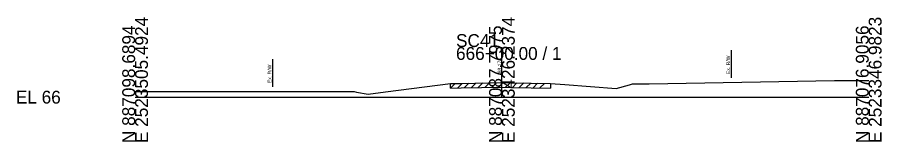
# Model space of a CAD drawing. Extents: x -26 to 183, y -10 to 24021.
# Drawn here: x -25.7 to 162.8, y 490.3 to 517.4 of the extents above; entities that cross this region are included whole.
import ezdxf

# ---------------------------------------------------------------- set-up
doc = ezdxf.new("R2010")
doc.units = 0
for name, color, linetype in [('RD_GPK_XS_Cell', 7, 'Continuous'), ('RD_XS_ExGround', 7, 'Continuous'), ('RD_XS_ExPaveRet', 7, 'Continuous'), ('RD_XS_ExRW', 7, 'Continuous'), ('RD_XS_TX_Elev_EX', 7, 'Continuous')]:
    doc.layers.add(name, color=color, linetype=linetype)

msp = doc.modelspace()

# ---------------------------------------------------------------- linework, layer by layer
at = {"layer": 'RD_GPK_XS_Cell'}
for p, q in [((80, 500), (80, 510.91)), ((0, 500), (80, 500)), ((80, 500), (160, 500))]:
    msp.add_line(p, q, dxfattribs=at)
at = {"layer": 'RD_XS_ExGround'}
for p, q in [((112.14, 502.92), (152.53, 503.61)), ((152.53, 503.61), (160, 503.64)), ((54.59, 501.13), (68.8, 502.95)), ((68.8, 502.95), (71.11, 503)), ((71.11, 503), (79.98, 503.17)), ((79.98, 503.17), (82.17, 503.13)), ((82.17, 503.13), (90.58, 502.97)), ((90.58, 502.97), (93.76, 502.73)), ((93.76, 502.73), (104.9, 501.88)), ((104.9, 501.88), (107.8, 502.68)), ((107.8, 502.68), (108.48, 502.9)), ((108.48, 502.9), (112.14, 502.92)), ((0, 501.25), (37.5, 501.26)), ((37.5, 501.26), (47.79, 501.2)), ((47.79, 501.2), (48.31, 501.08)), ((48.31, 501.08), (50.83, 500.63)), ((50.83, 500.63), (54.59, 501.13))]:
    msp.add_line(p, q, dxfattribs=at)
at = {"layer": 'RD_XS_ExPaveRet'}
for p, q in [((68.8, 501.95), (69.82, 502.97)), ((68.8, 501.95), (68.8, 502.95)), ((68.8, 501.95), (71.11, 502)), ((70.3, 501.98), (71.32, 503)), ((71.11, 502), (79.98, 502.17)), ((71.8, 502.01), (72.82, 503.03)), ((73.3, 502.04), (74.32, 503.06)), ((74.8, 502.07), (75.82, 503.09)), ((76.3, 502.1), (77.32, 503.12)), ((77.8, 502.13), (78.82, 503.15)), ((79.3, 502.16), (80.31, 503.17)), ((79.98, 502.17), (82.17, 502.13)), ((80.8, 502.16), (81.78, 503.14)), ((82.17, 502.13), (90.58, 501.97)), ((82.3, 502.13), (83.28, 503.11)), ((83.8, 502.1), (84.78, 503.08)), ((85.3, 502.07), (86.28, 503.05)), ((86.8, 502.04), (87.78, 503.02)), ((88.3, 502.01), (89.28, 502.99)), ((90.58, 502.97), (90.58, 501.97))]:
    msp.add_line(p, q, dxfattribs=at)
at = {"layer": 'RD_XS_ExRW'}
for p, q in [((130, 510.22), (130, 504.22)), ((30, 508.26), (30, 502.26))]:
    msp.add_line(p, q, dxfattribs=at)

# ---------------------------------------------------------------- texts
at = {"layer": 'RD_GPK_XS_Cell'}
for s, p in [('E 2523505.4924', (2.8, 490)), ('E 2523426.2374', (82.8, 490)), ('E 2523346.9823', (162.8, 490)), ('N 887098.6894', (0, 490)), ('N 887087.7975', (80, 490)), ('N 887076.9056', (160, 490))]:
    msp.add_text(s, height=2.8, rotation=90, dxfattribs=at).set_placement(p)
for s, p in [('SC41', (70, 510.91)), ('666+00.00 / 1', (70, 508.11)), ('EL 66', (-26, 498.6))]:
    msp.add_text(s, height=2.8, dxfattribs=at).set_placement(p)
at = {"layer": 'RD_XS_ExRW'}
for p in [(129.75, 505.01), (29.75, 503.04)]:
    msp.add_text('Ex. R/W ', height=0.8, rotation=90, dxfattribs=at).set_placement(p)
at = {"layer": 'RD_XS_TX_Elev_EX'}
msp.add_text('69.17', height=0.8, rotation=90, dxfattribs=at).set_placement((79.9, 505.17))

doc.saveas('drawing.dxf')
